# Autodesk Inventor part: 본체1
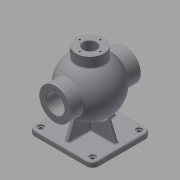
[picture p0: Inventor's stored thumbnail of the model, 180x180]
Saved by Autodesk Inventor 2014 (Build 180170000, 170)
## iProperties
Created: 2015-10
Part Number: 본체1
Material: Generic
Document SubType Name: Modeling
Designer: youjin13
Density: 1 g/cm^3
Appearance: Default
Author: youjin13
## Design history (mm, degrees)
sketch "Sketch1"
  geometry: L1 (50.5, -57.5)-(-50.5, -57.5); L2 (-62.5, -45.5)-(-62.5, 45.5); L3 (-50.5, 57.5)-(50.5, 57.5); L4 (62.5, 45.5)-(62.5, -45.5); L5 (62.5, -57.5)-(-62.5, 57.5); L6 (-62.5, -57.5)-(62.5, 57.5); A1 r 12 centre (-50.5, 45.5) between (-50.5, 57.5) and (-62.5, 45.5); A2 r 12 centre (50.5, 45.5) between (62.5, 45.5) and (50.5, 57.5); A3 r 12 centre (50.5, -45.5) between (50.5, -57.5) and (62.5, -45.5); A4 r 12 centre (-50.5, -45.5) between (-62.5, -45.5) and (-50.5, -57.5); 1 further point
  constraints: 12 end point, 8 point on circle, 8 point on line, 8 tangent, 4 centre point, 3 equal radius, 2 midpoint, 2 parallel, 1 horizontal, 1 perpendicular
  dimensions: "d0" = 125 distance of L5.end L6.end; "d1" = 115 distance of L6.end L5.start; "d2" = 12 radius of A1
extrude "Extrusion1" new body sketch "Sketch1" distance "d3" = 10; taper "d4" = 0 deg
sketch "Sketch2"
  geometry: A1 r 12 centre (-50.5, 45.5) between (-50.5, 57.5) and (-62.5, 45.5) reference; A2 r 12 centre (-50.5, -45.5) between (-62.5, -45.5) and (-50.5, -57.5) reference; A3 r 12 centre (50.5, -45.5) between (50.5, -57.5) and (62.5, -45.5) reference; A4 r 12 centre (50.5, 45.5) between (62.5, 45.5) and (50.5, 57.5) reference; 5 further points
  constraints: 4 coincident
hole "Hole1" sketch "Sketch2" at (-50.5, 45.5), (50.5, 45.5), (50.5, -45.5), (-50.5, -45.5) diameter "d5" = 8; stored, may be unused: countersink angle "d9" = 90 deg, drill point angle "d11" = 0 deg; dims "d6" = 6, "d7" = 12, "d8" = 3, "d10" = 8
sketch "Sketch3"
  geometry: L1 (50.5, 0)-(-50.5, 0) reference; L2 (0, 138)-(0, 32); A1 r 53 centre (0, 85) between (0, 32) and (0, 138); 3 further points
  constraints: 2 end point, 2 midpoint, 2 point on circle, 1 centre point, 1 coincident, 1 perpendicular, 1 vertical alignment
  dimensions: "d14" = 53 radius of A1; "d15" = 85 distance of point (0, 0) A1.centre
revolve "Revolution1" sketch "Sketch3" stored, may be unused: angle "d16" = 90 deg
workplane "Work Plane1"
sketch "Sketch4"
  geometry: C1 r 31 at (0, 85); 1 further point
  constraints: 1 centre point, 1 vertical alignment
  dimensions: "d18" = 62 diameter of C1; "d19" = 85 distance of point (0, 0) C1.centre
extrude "Extrusion2" join sketch "Sketch4" stored distance "d20" = 85 (= d19); taper "d21" = 0 deg
mirror "Mirror1"
sketch "Sketch5"
  geometry: L1 (0, 128)-(0, 42); C1 r 53 at (0, 85) reference; A1 r 43 centre (0, 85) between (0, 128) and (0, 42); 2 further points
  constraints: 2 coincident, 2 end point, 2 point on circle, 1 centre point, 1 midpoint, 1 vertical
  dimensions: "d22" = 86 diameter of A1
revolve "Revolution2" sketch "Sketch5" stored, may be unused: angle "d23" = 90 deg
sketch "Sketch6"
  geometry: C1 r 31 at (0, 0) reference; C2 r 17.5 at (0, 0); 1 further point
  constraints: 1 centre point, 1 coincident
  dimensions: "d24" = 35 diameter of C2
extrude "Extrusion3" cut sketch "Sketch6" distance "d25" = 16; taper "d26" = 0 deg
sketch "Sketch7"
  geometry: C1 r 17.5 at (0, 0) reference; C2 r 18.5 at (0, 0); 1 further point
  constraints: 1 centre point, 1 coincident
  dimensions: "d27" = 37 diameter of C2
extrude "Extrusion4" cut sketch "Sketch7" distance "d28" = 1.75; taper "d29" = 0 deg
sketch "Sketch8"
  geometry: C1 r 31 at (0, 0) reference; C2 r 17.5 at (0, 0); 1 further point
  constraints: 1 centre point, 1 coincident
  dimensions: "d30" = 35 diameter of C2
extrude "Extrusion5" cut sketch "Sketch8" stored distance "d31" = 1.75; taper "d32" = 0 deg
workplane "Work Plane2"
sketch "Sketch11"
  geometry: C1 r 27 at (0, 0); 1 further point
  constraints: 1 centre point, 1 coincident
  dimensions: "d47" = 54 diameter of C1
extrude "Extrusion8" join sketch "Sketch11" stored distance "d48" = 8; taper "d49" = 0 deg
sketch "Sketch12"
  geometry: C1 r 27 at (0, 0) reference; C2 r 13 at (0, 0)
  constraints: 1 centre point, 1 coincident
  dimensions: "d50" = 26 diameter of C2
extrude "Extrusion9" cut sketch "Sketch12" stored distance "d51" = 8; taper "d52" = 0 deg
chamfer "Chamfer1" distance "d53" = 1; stored, may be unused: second distance "d54" = 2, angle "d55" = 45 deg
sketch "Sketch13"
  geometry: C1 r 31 at (0, 0) reference; C2 r 18.5 at (0, 0) reference; A1 r 22.5 centre (0, 0) between (0, 22.5) and (-22.5, 0); 3 further points
  constraints: 4 point on circle, 2 horizontal alignment, 2 vertical alignment, 1 centre point, 1 coincident
  dimensions: "d56" = 45 diameter of A1
hole "Hole2" sketch "Sketch13" at (0, 22.5), (0, -22.5), (22.5, 0), (-22.5, 0) diameter "d57" = 3.242; stored, may be unused: countersink angle "d61" = 90 deg, drill point angle "d63" = 118 deg; dims "d58" = 12, "d59" = 12, "d60" = 3, "d62" = 15
sketch "Sketch14"
  geometry: C1 r 31 at (0, 0) reference; C2 r 18.5 at (0, 0) reference; A1 r 24 centre (0, 0) between (0, 24) and (24, 0); 3 further points
  constraints: 4 point on circle, 2 horizontal alignment, 2 vertical alignment, 1 centre point, 1 coincident
  dimensions: "d64" = 48 diameter of A1
hole "Hole3" sketch "Sketch14" at (0, -24), (0, 24), (24, 0), (-24, 0) diameter "d65" = 3.242; stored, may be unused: countersink angle "d69" = 90 deg, drill point angle "d71" = 118 deg; dims "d66" = 16, "d67" = 12, "d68" = 3, "d70" = 19
sketch "Sketch15"
  geometry: C1 r 27 at (0, 0) reference; C2 r 14 at (0, 0) reference; A1 r 20 centre (0, 0) between (0, 20) and (20, 0); 2 further points
  constraints: 4 point on circle, 2 horizontal alignment, 2 vertical alignment, 1 centre point, 1 coincident
  dimensions: "d72" = 40 diameter of A1
hole "Hole4" sketch "Sketch15" at (0, 20), (0, -20), (-20, 0), (20, 0) diameter "d73" = 3.242; stored, may be unused: countersink angle "d77" = 90 deg, drill point angle "d79" = 118 deg; dims "d74" = 9, "d75" = 12, "d76" = 3, "d78" = 11
workplane "Work Plane3"
sketch "Sketch16"
  geometry: L1 (-27, 150)-(27, 150) reference; 2 further points
  constraints: 1 vertical alignment, 1 other
  dimensions: "d81" = 10 distance from line of point (0, 140) L1
emboss "Emboss1" sketch "Sketch16" dims "d0" = 125, "d1" = 115, "d2" = 12, "d82" = 1, "d83" = 0
sketch "Sketch19"
  geometry: L1 (-57.5, 0)-(-57.5, 10) reference; L2 (45.5, 10)-(-45.5, 10) reference; L3 (-51.5, 10)-(-39.5, 10) reference; L4 (-45.5, 10)-(-57.5, 10) reference; L5 (39.5, 10)-(51.5, 10) reference; L6 (57.5, 10)-(45.5, 10) reference; L7 (57.5, 0)-(57.5, 10) reference; L8 (-33.719, 44.109)-(-47.5, 10); L9 (33.719, 44.109)-(47.5, 10); A1 r 53 centre (0, 85) between (42.988, 116) and (42.988, 54) reference; 1 further point
  constraints: 4 end point, 2 point on circle, 2 point on line
  dimensions: "d104" = 10 distance of L1.end L8.end; "d105" = 22 deg angle of L8 L1; "d106" = 22 deg angle of L7 L9; "d107" = 10 distance of L6.start L9.end
extrude "Extrusion10" join sketch "Sketch19" stored distance "d108" = 8; taper "d109" = 0 deg
sketch "Sketch20"
  geometry: L1 (-62.5, 0)-(-62.5, 10) reference; L2 (-56.5, 10)-(-44.5, 10) reference; L3 (-50.5, 10)-(-62.5, 10) reference; L4 (50.5, 10)-(-50.5, 10) reference; L5 (44.5, 10)-(56.5, 10) reference; L6 (-52.5, 10)-(-37.379, 47.426); L7 (37.379, 47.426)-(52.5, 10); L8 (62.5, 0)-(62.5, 10) reference; A1 r 53 centre (0, 85) between (-27, 130.607) and (27, 130.607) reference; 1 further point
  constraints: 4 end point, 2 point on circle, 2 point on line
  dimensions: "d111" = 22 deg angle of L1 L6; "d112" = 22 deg angle of L8 L7; "d113" = 10 distance of L8.end L7.end; "d114" = 10 distance from line of L1 L6.start
extrude "Extrusion11" join sketch "Sketch20" stored distance "d115" = 8; taper "d116" = 0 deg
fillet "Fillet2" dims "d117" = 3
fillet "Fillet3" dims "d118" = 3
fillet "Fillet4" dims "d119" = 3
fillet "Fillet5" dims "d120" = 3
body "Solid1"
other parameters: "d17" = -68, "d80" = -27.5
